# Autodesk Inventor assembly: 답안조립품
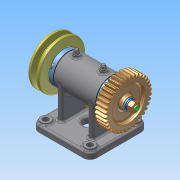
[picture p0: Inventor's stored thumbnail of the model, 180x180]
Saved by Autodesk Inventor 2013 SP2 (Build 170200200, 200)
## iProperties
Created: 2025-10
Part Number: 답안조립품
Document SubType Name: Assembly
Designer: 601
Author: 601
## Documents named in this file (17)
- C:\Users\601\Desktop\751003V1011\답안조립품.iam
- C:\Users\601\Desktop\751003V1011\본체.ipt
- C:\Users\601\Desktop\751003V1011\6각 머리 볼트 M6x0.75x8.ipt
- C:\Users\601\Desktop\751003V1011\실링.ipt
- C:\Users\601\Desktop\751003V1011\깊은 홈 볼 베어링 6002.ipt
- C:\Users\601\Desktop\751003V1011\축.ipt
- C:\Users\601\Desktop\751003V1011\가스켓.ipt
- C:\Users\601\Desktop\751003V1011\오일 실 15 25 4.ipt
- C:\Users\601\Desktop\751003V1011\커버.ipt
- C:\Users\601\Desktop\751003V1011\그리스 니플 M6x0.75.ipt
- C:\Users\601\Desktop\751003V1011\평행 키 3x3x12.ipt
- C:\Users\601\Desktop\751003V1011\6각 너트 M8x1.ipt
- C:\Users\601\Desktop\751003V1011\V 벨트 풀리.ipt
- C:\Users\601\Desktop\751003V1011\스프링 와셔 M8.ipt
- C:\Users\601\Desktop\751003V1011\평 와셔 M8.ipt
- C:\Users\601\Desktop\751003V1011\스퍼 기어.ipt
- C:\Users\601\Desktop\751003V1011\6각 구멍붙이 볼트 M4x10.ipt
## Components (14 placed, 6 different names)
1. 6각 머리 볼트 M6x0.75x8:1
2. 가스켓:1
3. 가스켓:2
4. 그리스 니플 M6x0.75:1 — 각도:3
5. 그리스 니플 M6x0.75:2 — 각도:4
6. 6각 너트 M8x1:1 — 각도:5
7. V 벨트 풀리:1
8. 6각 너트 M8x1:2
9. 6각 구멍붙이 볼트 M4x10:1 — 각도:2
10. 6각 구멍붙이 볼트 M4x10:3
11. 6각 구멍붙이 볼트 M4x10:4
12. 6각 구멍붙이 볼트 M4x10:2 — 각도:1
13. 6각 구멍붙이 볼트 M4x10:5
14. 6각 구멍붙이 볼트 M4x10:6
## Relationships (5: Angle 5)
- 각도:1 [Angle]: 6각 구멍붙이 볼트 M4x10:2
- 각도:2 [Angle]: 6각 구멍붙이 볼트 M4x10:1
- 각도:3 [Angle]: 그리스 니플 M6x0.75:1
- 각도:4 [Angle]: 그리스 니플 M6x0.75:2
- 각도:5 [Angle]: 6각 너트 M8x1:1
